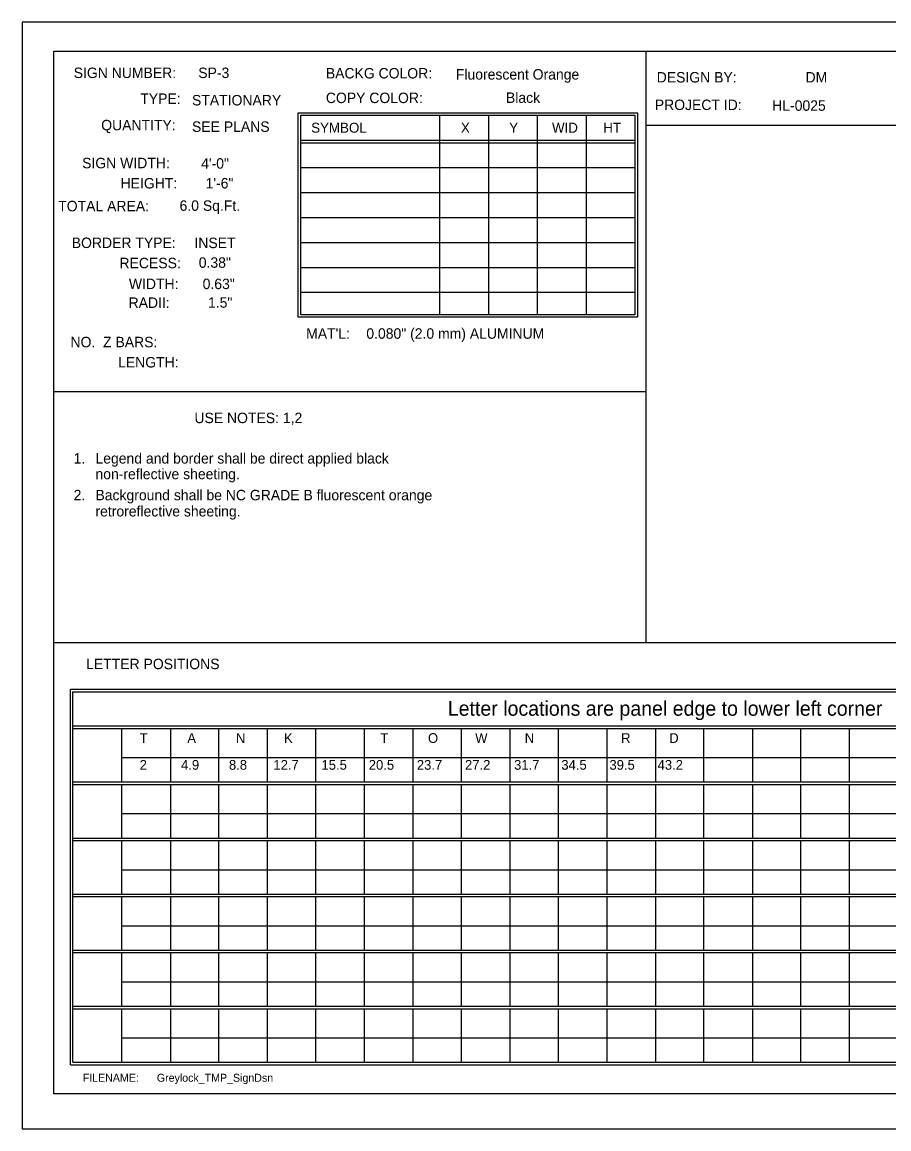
# Model space of a CAD drawing. Extents: x 1788.1 to 1851.2, y 237.2 to 283.4.
# Drawn here: x 1788.1 to 1804.44, y 237.17 to 258.03 of the extents above; entities that cross this region are included whole.
import ezdxf

# ---------------------------------------------------------------- set-up
doc = ezdxf.new("R2010")
doc.units = 0
for name, color, linetype in [('Old_Level_2', 7, 'Continuous'), ('Old_Level_3', 7, 'Continuous'), ('Old_Level_7', 7, 'Continuous'), ('Sheet Plot Border Outside CELL', 7, 'Continuous')]:
    doc.layers.add(name, color=color, linetype=linetype)

msp = doc.modelspace()

# ---------------------------------------------------------------- linework, layer by layer
at = {"layer": 'Old_Level_2'}
for p, q in [((1799.855, 257.479), (1799.855, 246.338)), ((1795.968, 256.27), (1795.968, 252.512)), ((1796.889, 256.27), (1796.889, 252.512)), ((1797.809, 256.27), (1797.809, 252.512)), ((1798.729, 256.27), (1798.729, 252.512)), ((1799.855, 256.081), (1817.019, 256.081)), ((1793.353, 255.8), (1799.649, 255.8)), ((1793.353, 255.754), (1799.649, 255.754)), ((1793.353, 255.284), (1799.649, 255.284)), ((1793.353, 254.814), (1799.649, 254.814)), ((1793.353, 254.344), (1799.649, 254.344)), ((1793.353, 253.875), (1799.649, 253.875)), ((1793.353, 253.405), (1799.649, 253.405)), ((1793.353, 252.935), (1799.649, 252.935)), ((1799.855, 251.061), (1788.693, 251.061)), ((1788.693, 246.338), (1799.855, 246.338)), ((1799.855, 246.338), (1817.019, 246.338)), ((1789.056, 244.765), (1810.834, 244.765)), ((1789.056, 244.719), (1810.834, 244.719)), ((1789.974, 244.719), (1789.974, 243.709)), ((1790.892, 244.719), (1790.892, 243.709)), ((1791.801, 244.719), (1791.801, 243.709)), ((1792.72, 244.719), (1792.72, 243.709)), ((1793.628, 244.719), (1793.628, 243.709)), ((1794.547, 244.719), (1794.547, 243.709)), ((1795.465, 244.719), (1795.465, 243.709)), ((1796.374, 244.719), (1796.374, 243.709)), ((1797.292, 244.719), (1797.292, 243.709)), ((1798.201, 244.719), (1798.201, 243.709)), ((1799.119, 244.719), (1799.119, 243.709)), ((1800.038, 244.719), (1800.038, 243.709)), ((1800.946, 244.719), (1800.946, 243.709)), ((1801.865, 244.719), (1801.865, 243.709)), ((1802.774, 244.719), (1802.774, 243.709)), ((1803.692, 244.719), (1803.692, 243.709)), ((1789.974, 244.168), (1810.834, 244.168)), ((1789.056, 243.709), (1810.834, 243.709)), ((1789.056, 243.663), (1810.834, 243.663)), ((1789.974, 243.663), (1789.974, 242.652)), ((1790.892, 243.663), (1790.892, 242.652)), ((1791.801, 243.663), (1791.801, 242.652)), ((1792.72, 243.663), (1792.72, 242.652)), ((1793.628, 243.663), (1793.628, 242.652)), ((1794.547, 243.663), (1794.547, 242.652)), ((1795.465, 243.663), (1795.465, 242.652)), ((1796.374, 243.663), (1796.374, 242.652)), ((1797.292, 243.663), (1797.292, 242.652)), ((1798.201, 243.663), (1798.201, 242.652)), ((1799.119, 243.663), (1799.119, 242.652)), ((1800.038, 243.663), (1800.038, 242.652)), ((1800.946, 243.663), (1800.946, 242.652)), ((1801.865, 243.663), (1801.865, 242.652)), ((1802.774, 243.663), (1802.774, 242.652)), ((1803.692, 243.663), (1803.692, 242.652)), ((1789.974, 243.112), (1810.834, 243.112)), ((1789.056, 242.652), (1810.834, 242.652)), ((1789.056, 242.606), (1810.834, 242.606)), ((1789.974, 242.606), (1789.974, 241.596)), ((1790.892, 242.606), (1790.892, 241.596)), ((1791.801, 242.606), (1791.801, 241.596)), ((1792.72, 242.606), (1792.72, 241.596)), ((1793.628, 242.606), (1793.628, 241.596)), ((1794.547, 242.606), (1794.547, 241.596)), ((1795.465, 242.606), (1795.465, 241.596)), ((1796.374, 242.606), (1796.374, 241.596)), ((1797.292, 242.606), (1797.292, 241.596)), ((1798.201, 242.606), (1798.201, 241.596)), ((1799.119, 242.606), (1799.119, 241.596)), ((1800.038, 242.606), (1800.038, 241.596)), ((1800.946, 242.606), (1800.946, 241.596)), ((1801.865, 242.606), (1801.865, 241.596)), ((1802.774, 242.606), (1802.774, 241.596)), ((1803.692, 242.606), (1803.692, 241.596)), ((1789.974, 242.055), (1810.834, 242.055)), ((1789.056, 241.596), (1810.834, 241.596)), ((1789.056, 241.55), (1810.834, 241.55)), ((1789.974, 241.55), (1789.974, 240.54)), ((1790.892, 241.55), (1790.892, 240.54)), ((1791.801, 241.55), (1791.801, 240.54)), ((1792.72, 241.55), (1792.72, 240.54)), ((1793.628, 241.55), (1793.628, 240.54)), ((1794.547, 241.55), (1794.547, 240.54)), ((1795.465, 241.55), (1795.465, 240.54)), ((1796.374, 241.55), (1796.374, 240.54)), ((1797.292, 241.55), (1797.292, 240.54)), ((1798.201, 241.55), (1798.201, 240.54)), ((1799.119, 241.55), (1799.119, 240.54)), ((1800.038, 241.55), (1800.038, 240.54)), ((1800.946, 241.55), (1800.946, 240.54)), ((1801.865, 241.55), (1801.865, 240.54)), ((1802.774, 241.55), (1802.774, 240.54)), ((1803.692, 241.55), (1803.692, 240.54)), ((1789.974, 240.999), (1810.834, 240.999)), ((1789.974, 240.657), (1789.974, 240.54)), ((1790.892, 240.657), (1790.892, 240.54)), ((1791.801, 240.657), (1791.801, 240.54)), ((1792.72, 240.657), (1792.72, 240.54)), ((1793.628, 240.657), (1793.628, 240.54)), ((1794.547, 240.657), (1794.547, 240.54)), ((1795.465, 240.657), (1795.465, 240.54)), ((1796.374, 240.657), (1796.374, 240.54)), ((1797.292, 240.657), (1797.292, 240.54)), ((1798.201, 240.657), (1798.201, 240.54)), ((1799.119, 240.657), (1799.119, 240.54)), ((1800.038, 240.657), (1800.038, 240.54)), ((1800.946, 240.657), (1800.946, 240.54)), ((1801.865, 240.657), (1801.865, 240.54)), ((1802.774, 240.657), (1802.774, 240.54)), ((1803.692, 240.657), (1803.692, 240.54)), ((1789.056, 240.54), (1810.834, 240.54)), ((1789.056, 240.54), (1810.834, 240.54)), ((1789.056, 240.494), (1810.834, 240.494)), ((1789.056, 240.494), (1810.834, 240.494)), ((1789.974, 240.494), (1789.974, 239.549)), ((1789.974, 240.494), (1789.974, 239.483)), ((1790.892, 240.494), (1790.892, 239.549)), ((1790.892, 240.494), (1790.892, 239.483)), ((1791.801, 240.494), (1791.801, 239.549)), ((1791.801, 240.494), (1791.801, 239.483)), ((1792.72, 240.494), (1792.72, 239.549)), ((1792.72, 240.494), (1792.72, 239.483)), ((1793.628, 240.494), (1793.628, 239.549)), ((1793.628, 240.494), (1793.628, 239.483)), ((1794.547, 240.494), (1794.547, 239.549)), ((1794.547, 240.494), (1794.547, 239.483)), ((1795.465, 240.494), (1795.465, 239.549)), ((1795.465, 240.494), (1795.465, 239.483)), ((1796.374, 240.494), (1796.374, 239.549)), ((1796.374, 240.494), (1796.374, 239.483)), ((1797.292, 240.494), (1797.292, 239.549)), ((1797.292, 240.494), (1797.292, 239.483)), ((1798.201, 240.494), (1798.201, 239.549)), ((1798.201, 240.494), (1798.201, 239.483)), ((1799.119, 240.494), (1799.119, 239.549)), ((1799.119, 240.494), (1799.119, 239.483)), ((1800.038, 240.494), (1800.038, 239.549)), ((1800.038, 240.494), (1800.038, 239.483)), ((1800.946, 240.494), (1800.946, 239.549)), ((1800.946, 240.494), (1800.946, 239.483)), ((1801.865, 240.494), (1801.865, 239.549)), ((1801.865, 240.494), (1801.865, 239.483)), ((1802.774, 240.494), (1802.774, 239.549)), ((1802.774, 240.494), (1802.774, 239.483)), ((1803.692, 240.494), (1803.692, 239.549)), ((1803.692, 240.494), (1803.692, 239.483)), ((1789.974, 239.942), (1810.834, 239.942)), ((1789.974, 239.942), (1810.834, 239.942)), ((1789.056, 239.483), (1810.834, 239.483)), ((1789.056, 239.483), (1810.834, 239.483)), ((1789.056, 239.437), (1810.834, 239.437)), ((1789.056, 239.437), (1810.834, 239.437)), ((1789.974, 239.601), (1789.974, 239.483)), ((1789.974, 239.437), (1789.974, 238.427)), ((1789.974, 239.437), (1789.974, 238.427)), ((1790.892, 239.601), (1790.892, 239.483)), ((1790.892, 239.437), (1790.892, 238.427)), ((1790.892, 239.437), (1790.892, 238.427)), ((1791.801, 239.601), (1791.801, 239.483)), ((1791.801, 239.437), (1791.801, 238.427)), ((1791.801, 239.437), (1791.801, 238.427)), ((1792.72, 239.601), (1792.72, 239.483)), ((1792.72, 239.437), (1792.72, 238.427)), ((1792.72, 239.437), (1792.72, 238.427)), ((1793.628, 239.601), (1793.628, 239.483)), ((1793.628, 239.437), (1793.628, 238.427)), ((1793.628, 239.437), (1793.628, 238.427)), ((1794.547, 239.601), (1794.547, 239.483)), ((1794.547, 239.437), (1794.547, 238.427)), ((1794.547, 239.437), (1794.547, 238.427)), ((1795.465, 239.601), (1795.465, 239.483)), ((1795.465, 239.437), (1795.465, 238.427)), ((1795.465, 239.437), (1795.465, 238.427)), ((1796.374, 239.601), (1796.374, 239.483)), ((1796.374, 239.437), (1796.374, 238.427)), ((1796.374, 239.437), (1796.374, 238.427)), ((1797.292, 239.601), (1797.292, 239.483)), ((1797.292, 239.437), (1797.292, 238.427)), ((1797.292, 239.437), (1797.292, 238.427)), ((1798.201, 239.601), (1798.201, 239.483)), ((1798.201, 239.437), (1798.201, 238.427)), ((1798.201, 239.437), (1798.201, 238.427)), ((1799.119, 239.601), (1799.119, 239.483)), ((1799.119, 239.437), (1799.119, 238.427)), ((1799.119, 239.437), (1799.119, 238.427)), ((1800.038, 239.601), (1800.038, 239.483)), ((1800.038, 239.437), (1800.038, 238.427)), ((1800.038, 239.437), (1800.038, 238.427)), ((1800.946, 239.601), (1800.946, 239.483)), ((1800.946, 239.437), (1800.946, 238.427)), ((1800.946, 239.437), (1800.946, 238.427)), ((1801.865, 239.601), (1801.865, 239.483)), ((1801.865, 239.437), (1801.865, 238.427)), ((1801.865, 239.437), (1801.865, 238.427)), ((1802.774, 239.601), (1802.774, 239.483)), ((1802.774, 239.437), (1802.774, 238.427)), ((1802.774, 239.437), (1802.774, 238.427)), ((1803.692, 239.601), (1803.692, 239.483)), ((1803.692, 239.437), (1803.692, 238.427)), ((1803.692, 239.437), (1803.692, 238.427)), ((1789.974, 238.886), (1810.834, 238.886)), ((1789.974, 238.886), (1810.834, 238.886)), ((1789.009, 238.381), (1810.834, 238.381)), ((1789.056, 238.427), (1810.834, 238.427)), ((1789.056, 238.427), (1810.834, 238.427)), ((1789.056, 238.381), (1810.834, 238.381))]:
    msp.add_line(p, q, dxfattribs=at)
for points in [[(1788.693, 257.479), (1817.019, 257.479), (1817.019, 237.834), (1788.693, 237.834)], [(1793.305, 256.318), (1799.698, 256.318), (1799.698, 252.465), (1793.305, 252.465)], [(1793.353, 256.27), (1799.649, 256.27), (1799.649, 252.512), (1793.353, 252.512)]]:
    msp.add_lwpolyline(points, close=True, dxfattribs=at)
for points in [[(1789.009, 239.549), (1789.009, 245.454), (1810.834, 245.454)], [(1789.056, 239.549), (1789.056, 245.408), (1810.834, 245.408)], [(1789.009, 238.381), (1789.009, 240.657)], [(1789.056, 238.427), (1789.056, 240.657)]]:
    msp.add_lwpolyline(points, dxfattribs=at)
at = {"layer": 'Sheet Plot Border Outside CELL'}
msp.add_lwpolyline([(1818.269, 258.025), (1788.097, 258.025), (1788.097, 237.172), (1818.269, 237.172)], close=True, dxfattribs=at)

# ---------------------------------------------------------------- texts
at = {"layer": 'Old_Level_2'}
for s, height, p in [('SIGN NUMBER:', 0.19685, (1789.07, 256.972)), ('BACKG COLOR:', 0.19685, (1793.824, 256.964)), ('DESIGN BY:', 0.1969, (1800.062, 256.888)), ('TYPE:', 0.1969, (1790.325, 256.486)), ('COPY COLOR:', 0.19685, (1793.824, 256.5)), ('PROJECT ID:', 0.19685, (1800.026, 256.369)), ('QUANTITY:', 0.1969, (1789.589, 255.987)), ('SIGN WIDTH:', 0.19685, (1789.229, 255.272)), ('HEIGHT:', 0.1969, (1789.954, 254.891)), ('TOTAL AREA:', 0.19685, (1788.778, 254.461)), ('BORDER TYPE:', 0.19685, (1789.033, 253.769)), ('RECESS:', 0.1969, (1789.933, 253.388)), ('WIDTH:', 0.1969, (1790.11, 252.995)), ('RADII:', 0.1969, (1790.105, 252.641)), ("MAT'L:", 0.1969, (1793.453, 252.06)), ('NO.  Z BARS:', 0.19685, (1789.009, 251.899)), ('LENGTH:', 0.1969, (1789.907, 251.518)), ('USE NOTES: 1,2', 0.19685, (1791.346, 250.47)), ('1.', 0.1969, (1789.068, 249.708)), ('Legend and border shall be direct applied black      ', 0.19685, (1789.48, 249.708)), ('2.', 0.1969, (1789.068, 249.016)), ('LETTER POSITIONS', 0.19685, (1789.304, 245.834)), ('Letter locations are panel edge to lower left corner', 0.27559, (1796.123, 244.956))]:
    msp.add_text(s, height=height, rotation=360, dxfattribs=at).set_placement(p)
for s, height, p in [('DM', 0.1969, (1802.868, 256.888)), ('HL-0025', 0.1969, (1802.239, 256.355)), ('SYMBOL', 0.1879, (1793.547, 255.942)), ('X', 0.188, (1796.37, 255.942)), ('Y', 0.188, (1797.281, 255.942)), ('WID', 0.1879, (1798.088, 255.942)), ('HT', 0.1879, (1799.054, 255.942)), ('0.080" (2.0 mm) ALUMINUM', 0.19685, (1794.587, 252.06)), ('non-reflective sheeting.', 0.19685, (1789.48, 249.413)), ('Background shall be NC GRADE B fluorescent orange', 0.19685, (1789.48, 249.016)), ('retroreflective sheeting.', 0.19685, (1789.48, 248.711)), ('T', 0.184, (1790.313, 244.444)), ('A', 0.184, (1791.212, 244.444)), ('N', 0.184, (1792.128, 244.444)), ('K', 0.184, (1793.036, 244.444)), ('T', 0.184, (1794.851, 244.444)), ('O', 0.184, (1795.75, 244.444)), ('W', 0.184, (1796.64, 244.444)), ('N', 0.184, (1797.574, 244.444)), ('R', 0.184, (1799.39, 244.444)), ('D', 0.184, (1800.298, 244.444)), ('2', 0.184, (1790.313, 243.939)), ('4.9', 0.1837, (1791.094, 243.939)), ('8.8', 0.1837, (1791.997, 243.939)), ('12.7', 0.1837, (1792.835, 243.939)), ('15.5', 0.1837, (1793.742, 243.939)), ('20.5', 0.1837, (1794.633, 243.939)), ('23.7', 0.1837, (1795.54, 243.939)), ('27.2', 0.1837, (1796.448, 243.939)), ('31.7', 0.1837, (1797.373, 243.939)), ('34.5', 0.1837, (1798.264, 243.939)), ('39.5', 0.1837, (1799.171, 243.939)), ('43.2', 0.1837, (1800.079, 243.939))]:
    msp.add_text(s, height=height, dxfattribs=at).set_placement(p)
at = {"layer": 'Old_Level_3'}
for s, p in [('SP-3', (1791.419, 256.972)), ('Black', (1797.22, 256.504))]:
    msp.add_text(s, height=0.1969, dxfattribs=at).set_placement(p)
for s, height, p in [('Fluorescent Orange', 0.19685, (1796.275, 256.943)), ('STATIONARY', 0.1969, (1791.3, 256.456)), ('SEE PLANS', 0.1969, (1791.3, 255.958)), ('4\'-0"', 0.1969, (1791.473, 255.264)), ('1\'-6"', 0.1969, (1791.557, 254.892)), ('6.0 Sq.Ft.', 0.1969, (1791.066, 254.47)), ('INSET', 0.1969, (1791.346, 253.768)), ('0.38"', 0.1969, (1791.428, 253.397)), ('0.63"', 0.1969, (1791.501, 252.995)), ('1.5"', 0.1969, (1791.602, 252.644))]:
    msp.add_text(s, height=height, rotation=360, dxfattribs=at).set_placement(p)
at = {"layer": 'Old_Level_7'}
for s, height, p in [('FILENAME:', 0.1497, (1789.241, 238.06)), ('Greylock_TMP_SignDsn', 0.14974, (1790.638, 238.06))]:
    msp.add_text(s, height=height, rotation=360, dxfattribs=at).set_placement(p)

doc.saveas('drawing.dxf')
